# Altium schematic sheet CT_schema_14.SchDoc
size 144 x 119 mm
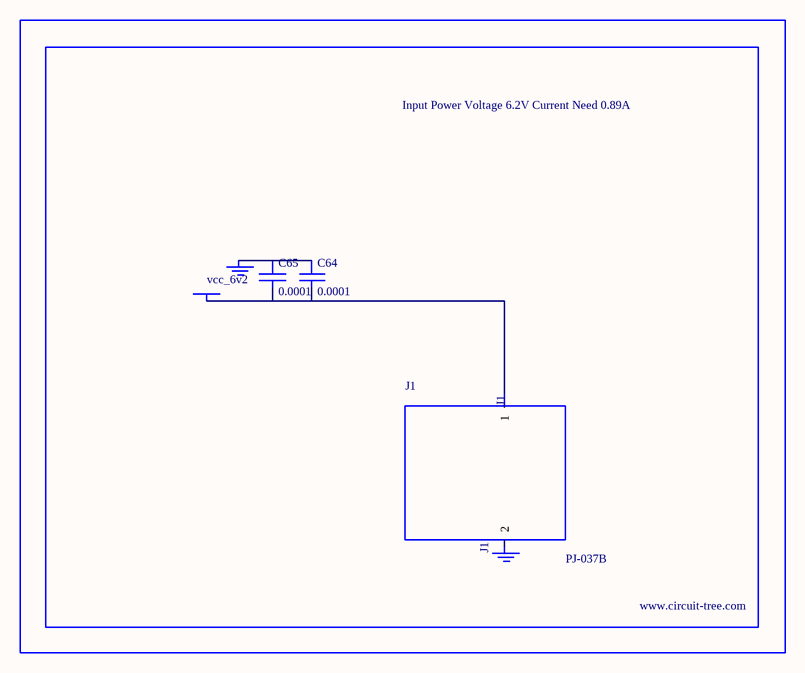
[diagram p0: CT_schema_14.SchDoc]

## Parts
BORDER13  (no value)
C64  0.0001  [EXV-9H]
C65  0.0001  [EXV-9H]
GND_INSTANCE_13_0  (no value)
GND_INSTANCE_13_1  (no value)
J1  PJ-037B  [PJ-037B_PACKAGE]
POWER_INSTANCE_13_0  vcc_6v2

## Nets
NetC64_1: C64.1 C65.1 GND_INSTANCE_13_0.0(GND)
NetC64_2: C64.2 C65.2 J1.1 POWER_INSTANCE_13_0.0(PWR)

Not connected (* = marked no-connect by the designer): GND_INSTANCE_13_1 0(GND); J1 2

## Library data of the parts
BORDER13 = BORDER_PAGE13
C64 C65 = EDK107M035A9HAA
GND_INSTANCE_13_0 GND_INSTANCE_13_1 = GND
POWER_INSTANCE_13_0 = PWR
